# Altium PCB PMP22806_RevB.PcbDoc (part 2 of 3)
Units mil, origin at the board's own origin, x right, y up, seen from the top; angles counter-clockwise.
Board outline 5500 x 3040 mil, 4 copper layers (Top Layer, Signal Layer 1, Signal Layer 2, Bottom Layer), stack 61.2 mil thick; 196 components, 100 nets, 518 pads, 186 vias.
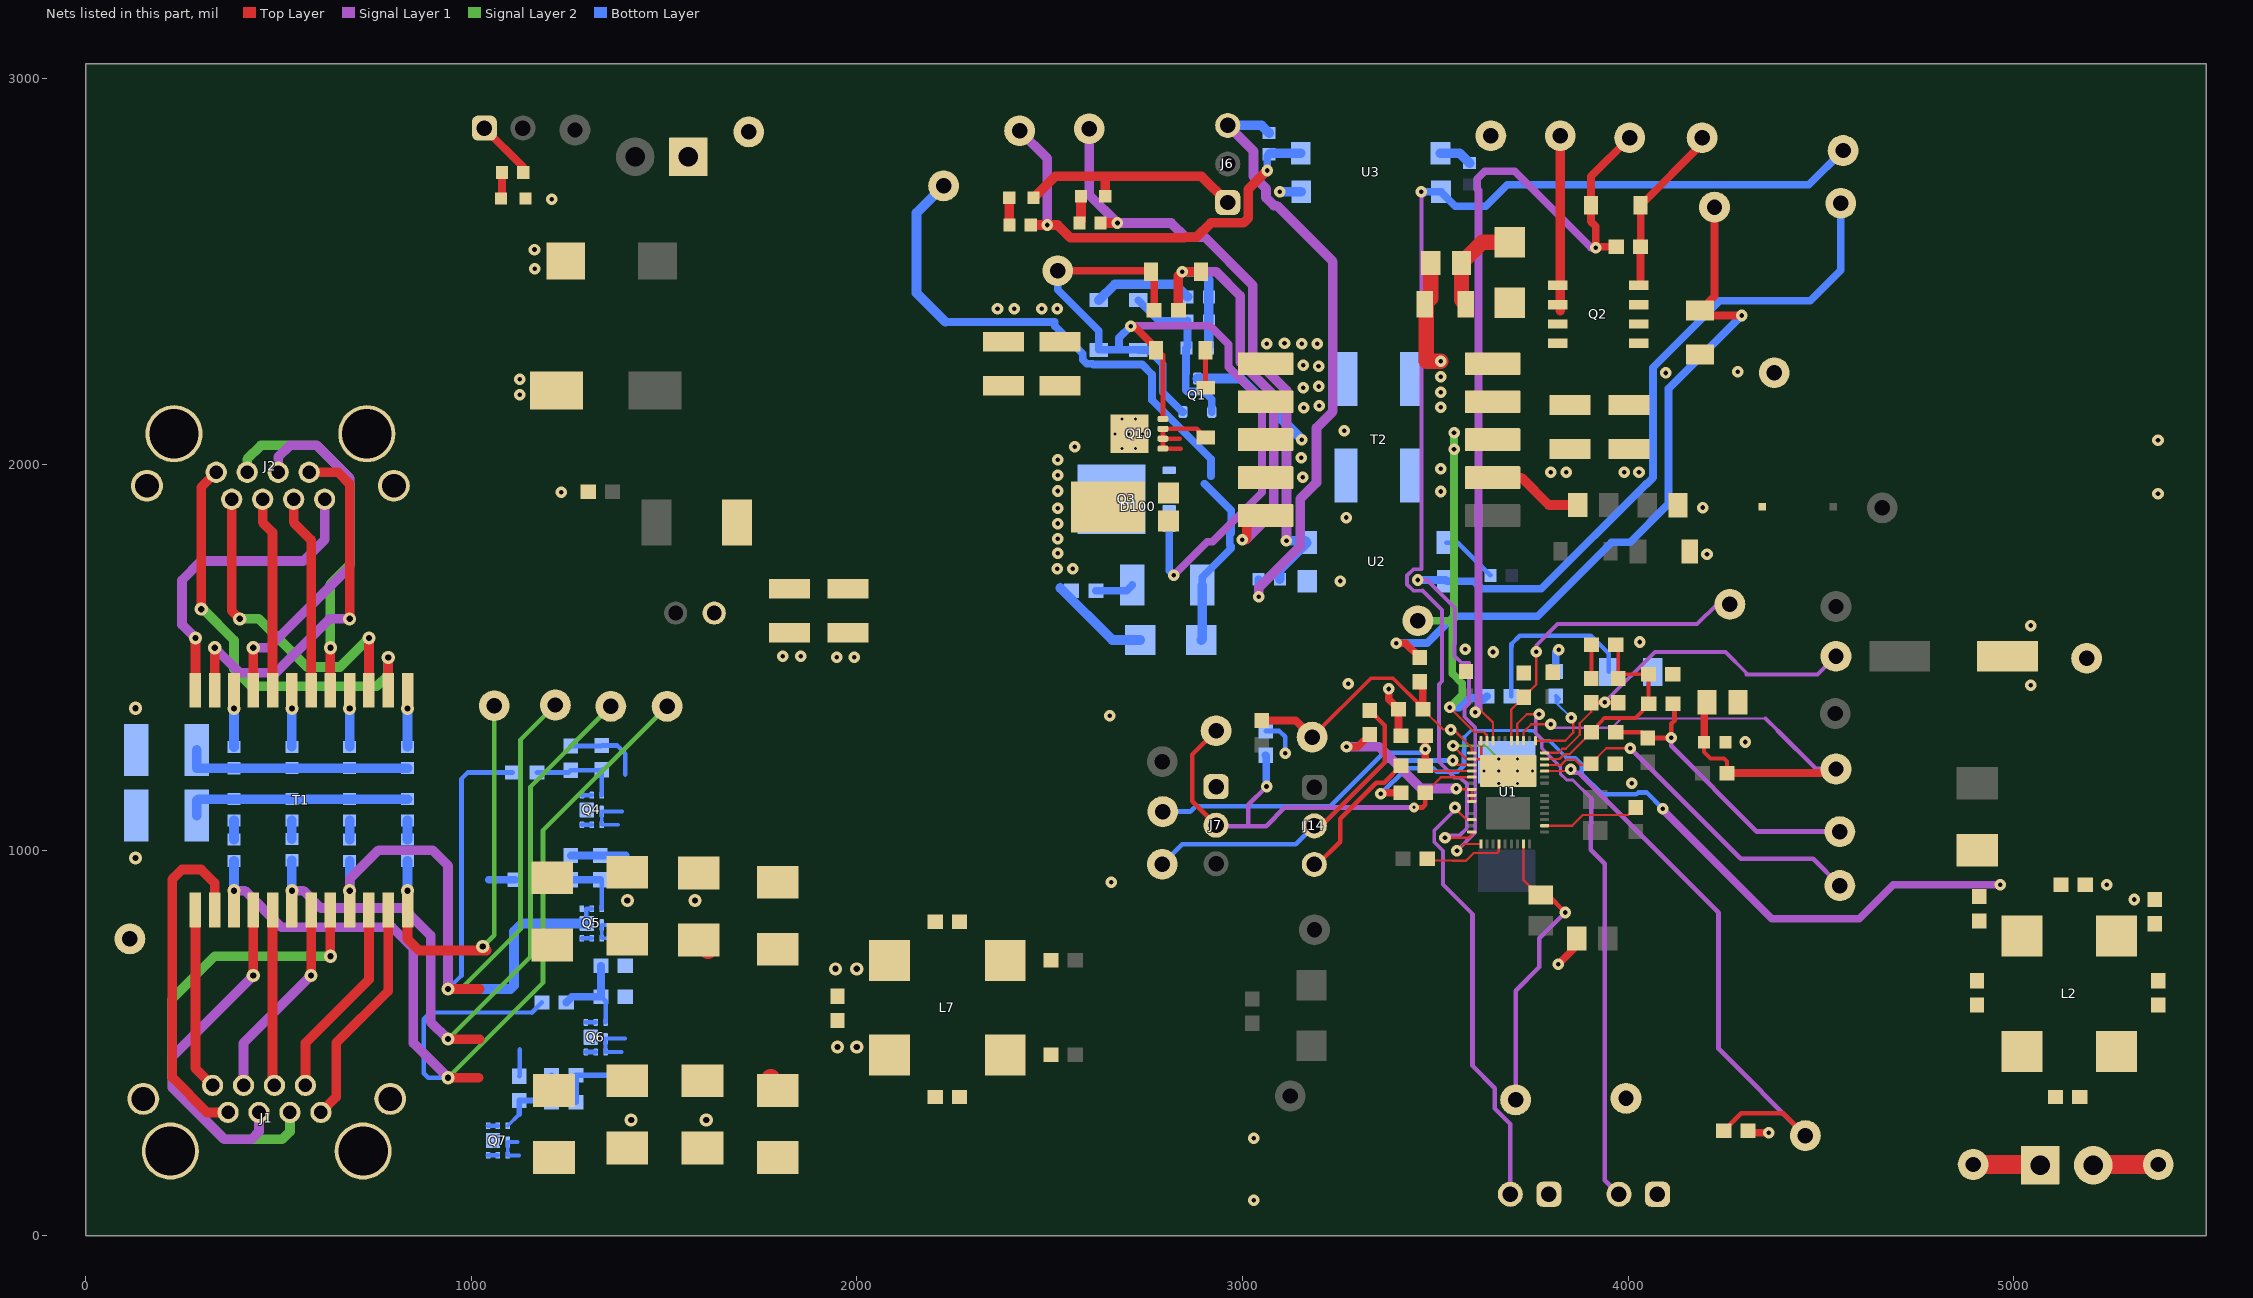
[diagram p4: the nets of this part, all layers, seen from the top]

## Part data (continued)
L4: library part CMP-0063890-1, "Inductor, Shielded Drum Core, Ferrite, 150 nH, 30 A, 0.000235 ohm, SMD", Manufacturer="Wurth Elektronik", Supplier Part Number 1=732-3698-1-ND, Value1="0.000235 ohm", Value2=30A, ValueDisplayed=150nH
Logo1: library part CMP-0074847-1, "FCC_disclaimer"
Logo2: library part CMP-0074769-1
Q1: library part CMP-0000326-2, "Transistor, PNP, 40 V, 0.2 A, SOT-23", Manufacturer="Diodes Inc.", Supplier Part Number 1=MMBT3906-FDICT-ND, Value1="0.2 A", Value2=400
Q2: library part CMP-0001058-1, "MOSFET, N-CH, 150 V, 4.6 A, PQFN08A", Alternate Manufacturer=None, Manufacturer="Fairchild Semiconductor", Supplier Part Number 1=FDMS86252CT-ND, Value1=0, Value2="11 nC"
Q3: library part CMP-0000708-1, "MOSFET, N-CH, 40 V, 15 A, DQJ0008A (VSONP-8)", Alternate Manufacturer=None, Manufacturer="Texas Instruments", Supplier Part Number 1=296-30572-1-ND, Value1=0.009, Value2="7.7 nC"
Q4 Q5 Q6 Q7: library part CMP-0000968-2, "MOSFET, N-CH, 100 V, 4.5 A, DQK0006C (WSON-6)", Alternate Manufacturer=None, Manufacturer="Texas Instruments"
Q10: library part CMP-0000589-2, "MOSFET, N-CH, 30 V, 19 A, DNH0008A (VSONP-8)", Alternate Manufacturer=None, Manufacturer="Texas Instruments", Supplier Part Number 1=296-39995-1-ND, Value1=0.006, Value2="13 nC"
R1 R2 R3 R4 R5 R6 R7 R8: library part CMP-0022590-4, "RES, 75.0, 1%, 0.1 W, AEC-Q200 Grade 0, 0603", Manufacturer=Vishay-Dale, PartNumber=CRCW060375R0FKEA, Power_W=100mW, Supplier Part Number 1=541-75.0HCT-ND, TempCo="100 ppm/C", Tolerance_%=1%, Value2=0.1W, Value_Code=75R0, ValueDisplayed=75.0
R9 R37: library part CMP-0021990-4, "RES, 100 k, 1%, 0.1 W, AEC-Q200 Grade 0, 0603", Manufacturer=Vishay-Dale, Power_W=100mW, Supplier Part Number 1=541-100KHCT-ND, TempCo="100 ppm/C", Tolerance_%=1%, Value2=0.1W, Value_Code=100k
R10: library part CMP-0022453-4, "RES, 4.42 k, 1%, 0.1 W, AEC-Q200 Grade 0, 0603", Manufacturer=Vishay-Dale, Power_W=100mW, Supplier Part Number 1=541-4.42KHCT-ND, TempCo="100 ppm/C", Tolerance_%=1%, Value2=0.1W, Value_Code=4k42, ValueDisplayed=4.42k
R11: library part CMP-0025821-4, "RES, 4.7, 5%, 0.1 W, AEC-Q200 Grade 0, 0603", Manufacturer=Vishay-Dale, PartNumber=CRCW06034R70JNEA, Power_W=100mW, Supplier Part Number 1=541-4.7GCT-ND, TempCo="200 ppm/C", Tolerance_%=5%, Value2=0.1W, Value_Code=4R70, ValueDisplayed=4.7
R12: library part CMP-0022458-4, "RES, 4.99 k, 1%, 0.1 W, AEC-Q200 Grade 0, 0603", Manufacturer=Vishay-Dale, Power_W=100mW, Supplier Part Number 1=541-4.99KHCT-ND, TempCo="100 ppm/C", Tolerance_%=1%, Value2=0.1W, Value_Code=4k99, ValueDisplayed=4.99k
R13: library part CMP-0018666-3, "RES, 39 k, 5%, 0.25 W, AEC-Q200 Grade 0, 1206", Manufacturer=Vishay-Dale, PartNumber=CRCW120639K0JNEA, Power_W=250mW, Supplier Part Number 1=541-39KECT-ND, TempCo="200 ppm/C", Tolerance_%=5%, Value2=0.25W, Value_Code=39k0, ValueDisplayed=39k
R14: library part CMP-0025821-4, "RES, 4.7, 5%, 0.1 W, AEC-Q200 Grade 0, 0603", Manufacturer=Vishay-Dale, Power_W=100mW, Supplier Part Number 1=541-4.7GCT-ND, TempCo="200 ppm/C", Tolerance_%=5%, Value2=0.1W, Value_Code=4R70, ValueDisplayed=4.7
R15 R17 R20 R21: "RES, 1.00 M, 1%, 0.1 W, AEC-Q200 Grade 0, 0603", Manufacturer=Vishay-Dale, PartNumber=CRCW06031M00FKEA, Power_W=100mW, Supplier Part Number 1=541-1.00MHCT-ND, TempCo="100 ppm/C", Tolerance_%=1%, Value2=0.1W, Value_Code=1M00, ValueDisplayed=1.00M
R16: library part CMP-0021831-3, "RES, 3.90, 1%, 0.125 W, AEC-Q200 Grade 0, 0805", Manufacturer=Panasonic, Power_W=125mW, Supplier Part Number 1=P3.9DCT-ND, TempCo="200 ppm/C", Tolerance_%=1%, Value2=0.125W, Value_Code=3R90, ValueDisplayed=3.90
R18: library part CMP-0017789-3, "RES, 0.12, 1%, 0.25 W, AEC-Q200 Grade 0, 1206", Manufacturer=Panasonic, Power_W=250mW, Supplier Part Number 1=P.39RCT-ND, TempCo="250 ppm/C", Tolerance_%=1%, Value2=0.25W, Value_Code=R390, ValueDisplayed=0.12
R19: library part CMP-0022895-5, "RES, 1.00 k, 1%, 0.1 W, 0603", Manufacturer=Yageo, Power_W=100mW, Supplier Part Number 1=311-1.00KHRCT-ND, TempCo="100 ppm/C", Tolerance_%=1%, Value2=0.1W, Value_Code=1k00, ValueDisplayed=1.00k
R22 R25 R26 R29: "RES, 232 k, 1%, 0.1 W, AEC-Q200 Grade 0, 0603", Manufacturer=Vishay-Dale, PartNumber=CRCW0603232KFKEA, Power_W=100mW, Supplier Part Number 1=541-232KHCT-ND, TempCo="100 ppm/C", Tolerance_%=1%, Value2=0.1W, Value_Code=232k
R24: library part CMP-0022447-4, "RES, 49.9 k, 1%, 0.1 W, AEC-Q200 Grade 0, 0603", Manufacturer=Vishay-Dale, Power_W=100mW, Supplier Part Number 1=541-49.9KHCT-ND, TempCo="100 ppm/C", Tolerance_%=1%, Value2=0.1W, Value_Code=49k9, ValueDisplayed=49.9k
R27: library part CMP-0021169-3, "RES, 31.6, 1%, 0.125 W, AEC-Q200 Grade 0, 0805", Manufacturer=Vishay-Dale, Power_W=125mW, Supplier Part Number 1=541-31.6CCT-ND, TempCo="100 ppm/C", Tolerance_%=1%, Value2=0.125W, Value_Code=31R6, ValueDisplayed=31.6
R28: library part CMP-0022951-5, "RES, 25.5 k, 1%, 0.1 W, 0603", Manufacturer=Yageo, Power_W=100mW, Supplier Part Number 1=311-25.5KHRCT-ND, TempCo="100 ppm/C", Tolerance_%=1%, Value2=0.1W, Value_Code=25k5, ValueDisplayed=25.5k
R30 R55 R56 R57 R58: library part CMP-0025874-4, "RES, 0, 5%, 0.1 W, AEC-Q200 Grade 0, 0603", Manufacturer=Panasonic, Power_W=100mW, Supplier Part Number 1=P0.0GCT-ND, TempCo="600 ppm/C", Tolerance_%=5%, Value2=0.1W, Value_Code=0000, ValueDisplayed=0
R31: library part CMP-0022003-4, "RES, 10.0, 1%, 0.1 W, AEC-Q200 Grade 0, 0603", Manufacturer=Vishay-Dale, Power_W=100mW, Supplier Part Number 1=541-10.0HCT-ND, TempCo="100 ppm/C", Tolerance_%=1%, Value2=0.1W, Value_Code=10R0, ValueDisplayed=10.0
R32: library part CMP-0022008-4, "RES, 110 k, 1%, 0.1 W, AEC-Q200 Grade 0, 0603", Manufacturer=Vishay-Dale, Power_W=100mW, Supplier Part Number 1=541-110KHCT-ND, TempCo="100 ppm/C", Tolerance_%=1%, Value2=0.1W, Value_Code=110k
R33 R36 R48 R59 R60 R61 R64 R65: library part CMP-0021998-4, "RES, 10.0 k, 1%, 0.1 W, AEC-Q200 Grade 0, 0603", Manufacturer=Vishay-Dale, Power_W=100mW, Supplier Part Number 1=541-10.0KHCT-ND, TempCo="100 ppm/C", Tolerance_%=1%, Value2=0.1W, Value_Code=10k0, ValueDisplayed=10.0k
R34: library part CMP-0025703-4, "RES, 10, 5%, 0.1 W, AEC-Q200 Grade 0, 0603", Manufacturer=Vishay-Dale, Power_W=100mW, Supplier Part Number 1=541-10GCT-ND, TempCo="200 ppm/C", Tolerance_%=5%, Value2=0.1W, Value_Code=10R0, ValueDisplayed=10
R35: library part CMP-0022944-5, "RES, 24.9 k, 1%, 0.1 W, 0603", Manufacturer=Yageo, Power_W=100mW, Supplier Part Number 1=311-24.9KHRCT-ND, TempCo="100 ppm/C", Tolerance_%=1%, Value2=0.1W, Value_Code=24k9, ValueDisplayed=24.9k
R38: library part CMP-0022452-4, "RES, 4.32 k, 1%, 0.1 W, AEC-Q200 Grade 0, 0603", Manufacturer=Vishay-Dale, Power_W=100mW, Supplier Part Number 1=541-4.32KHCT-ND, TempCo="100 ppm/C", Tolerance_%=1%, Value2=0.1W, Value_Code=4k32, ValueDisplayed=4.32k
R40: library part CMP-0022931-4, "RES, 237 k, 1%, 0.1 W, 0603", Manufacturer=Yageo, Power_W=100mW, Supplier Part Number 1=311-237KHRCT-ND, TempCo="100 ppm/C", Tolerance_%=1%, Value2=0.1W, Value_Code=237k
R41: library part CMP-0020539-3, "RES, 3.3 k, 5%, 0.125 W, AEC-Q200 Grade 0, 0805", Manufacturer=Vishay-Dale, Power_W=125mW, Supplier Part Number 1=541-3.3KACT-ND, TempCo="200 ppm/C", Tolerance_%=5%, Value2=0.125W, Value_Code=3k30, ValueDisplayed=3.3k
R42: library part CMP-0022532-4, "RES, 60.4 k, 1%, 0.1 W, AEC-Q200 Grade 0, 0603", Manufacturer=Vishay-Dale, Power_W=100mW, Supplier Part Number 1=541-60.4KHCT-ND, TempCo="100 ppm/C", Tolerance_%=1%, Value2=0.1W, Value_Code=60k4, ValueDisplayed=60.4k
R43: library part CMP-0018698-3, "RES, 51, 5%, 0.25 W, AEC-Q200 Grade 0, 1206", Manufacturer=Vishay-Dale, Power_W=250mW, Supplier Part Number 1=541-51ECT-ND, TempCo="200 ppm/C", Tolerance_%=5%, Value2=0.25W, Value_Code=51R0, ValueDisplayed=51
R47: library part CMP-0022445-4, "RES, 499 k, 1%, 0.1 W, AEC-Q200 Grade 0, 0603", Manufacturer=Vishay-Dale, Power_W=100mW, Supplier Part Number 1=541-499KHCT-ND, TempCo="100 ppm/C", Tolerance_%=1%, Value2=0.1W, Value_Code=499k
R68: library part CMP-0022587-4, "RES, 750 k, 1%, 0.1 W, AEC-Q200 Grade 0, 0603", Manufacturer=Vishay-Dale, Power_W=100mW, Supplier Part Number 1=541-750KHCT-ND, TempCo="100 ppm/C", Tolerance_%=1%, Value2=0.1W, Value_Code=750k
R69: library part CMP-0016180-3, "RES, 7.5, 5%, 0.75 W, AEC-Q200 Grade 0, 2010", Manufacturer=Vishay-Dale, Power_W=750mW, Supplier Part Number 1=541-7.5WCT-ND, TempCo="200 ppm/C", Tolerance_%=5%, Value2=0.75W, Value_Code=7R50, ValueDisplayed=7.5
T1: library part CMP-0030597-1, "Transformer, 350 uH, SMT", Manufacturer="Wurth Elektronik", ValueDisplayed=350uH
T2: library part CMP-0087730-2, "Flyback transformer for PoE applications", Manufacturer=LinkCom, PartNumber=LDT1069-50R, ValueDisplayed=70pF
TP1 TP6 TP12 TP18 TP43 TP45: library part CMP-0055137-1, "Test Point, Miniature, Red, TH", Color=Red, Manufacturer=Keystone, Supplier Part Number 1=36-5000-ND
TP2 TP7 TP8 TP14 TP30 TP37 TP38 TP44: library part CMP-0055138-1, "Test Point, Miniature, Black, TH", Color=Black, Manufacturer=Keystone, Supplier Part Number 1=36-5001-ND
TP3 TP5 TP9 TP10 TP15 TP16 TP17 TP19 TP20 TP22 TP23 TP24 TP25 TP26 TP27 TP32: library part CMP-0055139-1, "Test Point, Miniature, White, TH", Color=White, Manufacturer=Keystone, Supplier Part Number 1=36-5002-ND
TP4 TP11 TP13 TP21 TP28 TP29 TP33 TP34 TP39 TP40 TP42: library part CMP-0055140-1, "Test Point, Miniature, Orange, TH", Color=Orange, Manufacturer=Keystone, Supplier Part Number 1=36-5003-ND
U1: library part CMP-0089620-1, "IEEE 802.3bt Type 3 Class 1-4 PoE PD with No-Opto Flyback DC-DC Controller", Manufacturer="Texas Instruments", Operating Temperature Range="-40°C to +125°C", Switching Frequency=250kHz
U2 U3: library part CMP-0006165-3, "Optocoupler, 5 kV, 300-600% CTR, SMT", Manufacturer="Fairchild Semiconductor", Supplier Part Number 1=FOD817DS-ND, Voltage_Isolation_Vrms=5kV

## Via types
v1: diameter 30, hole 12, Top Layer to Bottom Layer, 104 vias
v2: diameter 34, hole 16, Top Layer to Bottom Layer, 37 vias
v3: diameter 30, hole 12, Top Layer to Bottom Layer, tented both sides, 22 vias
v4: diameter 19.68, hole 7.87, Top Layer to Bottom Layer, 19 vias
v5: diameter 20, hole 8, Top Layer to Bottom Layer, 2 vias
v6: diameter 26, hole 9, Top Layer to Bottom Layer, tented both sides, 1 vias
v7: diameter 19.68, hole 7.87, Top Layer to Bottom Layer, tented both sides, 1 vias

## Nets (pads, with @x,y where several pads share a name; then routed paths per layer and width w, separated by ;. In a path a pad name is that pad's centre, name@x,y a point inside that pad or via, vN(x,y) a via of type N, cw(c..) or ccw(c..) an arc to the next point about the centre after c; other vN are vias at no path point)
APD: J7.2 R9.1 R10.2 TP5.1 U1.5 | length 1238.6
  Top Layer w6: R9.1@3474.24,1149.02 3514.65,1189.42 U1.5@3594.85,1189.42
  Top Layer w12: J7.2@2931.67,1064.8 2870,1126.47 2870,1248.18 TP5.1@2931.67,1309.85 ; v6(3445,1110.86) 3467.65,1110.86 3474.24,1117.46 R9.1@3474.24,1149.02
  Signal Layer 1 w12: J7.2@2931.67,1064.8 2934.14,1062.33 3015,1062.33 ; v3(3062.64,1165.21) 3015,1117.57 3015,1062.33 ; v6(3445,1110.86) 3110.2,1110.86 3061.67,1062.33 3015,1062.33
  Bottom Layer w20: R10.2@3060.14,1246.23 3061.67,1244.7 v3@3061.67,1162.33
APDO: TP33.1 U1.13 U3.2 | length 3092.8
  Top Layer w6: v1(3525.32,1032.61) 3587.69,1032.61 3594.85,1039.77 U1.13@3594.85,1047.69
  Signal Layer 1 w10: v3(3464.21,2707.02) 3464.21,1728.56 3443.57,1728.56 3427.24,1712.23 3427.24,1689.14 3443.57,1672.81 3466.66,1672.81 3466.98,1673.12 3517.59,1622.5 3517.59,1438.04 3509.58,1430.03 3509.58,1229.5 3551.35,1187.72 3565.76,1187.72 3582.09,1171.4 3582.09,1097.31 3581.72,1096.93 3581.72,1056.62 3562.88,1037.77 3530.48,1037.77 v1(3525.32,1032.61)
  Signal Layer 1 w20: v3(3464.21,2707.02) v3@3468.23,2703
  Bottom Layer w20: v3(3464.21,2707.02) 3464.81,2707.61 U3.2@3514.8,2707.61 3552.41,2670 3630.97,2670 3686.46,2725.48 4468.69,2725.48 TP33.1@4557.62,2814.41
BSP: C1.1 C6.2 J1.9 J1.10 J1.11 J1.12 J2.9 J2.10 J2.11 J2.12 TP42.1
  other v2: 130,980 130,1367.99
CP: C42.1 T2.3 TP28.1 U1.44 | length 1093.4
  Top Layer w6: v3(3537.45,1370.21) 3601.07,1306.59 3625.76,1306.59 3633.28,1299.07 3633.28,1288.72 3633.28,1283.91 U1.44@3634.22,1283.91
  Top Layer w8: v3(3537.45,1370.21) v3@3540.49,1370.21
  Signal Layer 2 w20: TP28.1@3455.12,1595.17 3543.97,1595.17 ; v3@3543.52,1370.21 v3(3537.45,1370.21) 3570.33,1403.08 3570.33,1432.1 3543.97,1458.45 3543.97,1595.17 ; v1(3548.8,2082.66) v1(3548.8,2040) 3548.8,1600 3543.97,1595.17
  Bottom Layer w20: v3(3537.45,1370.21) 3562.28,1370.21 3574.68,1382.61 3576.55,1380.75 3590.53,1394.73 3617.76,1394.73 3623.52,1388.97 C42.1@3634.04,1399.49
CS: C25.1 R19.1 R68.2 TP15.1 U1.1 | length 787.1
  Top Layer w6: C25.1@3467.92,1365.64 3520.75,1312.8 v1(3540,1312.8) 3547.18,1312.8 3594.85,1265.13 U1.1@3594.85,1252.41
  Top Layer w10: TP15.1@3180.79,1293.42 3333.44,1446.07 3390.76,1446.07 C25.1@3467.92,1368.92
  Top Layer w20: R68.2@3050,1336.5 3137.72,1336.5 TP15.1@3180.79,1293.42 ; R19.1@3459.5,1436.98 3467.92,1428.56 3467.92,1368.92 C25.1@3467.92,1365.64
GND: C11.1 C16.2 C17.2 C18.2 C19.2 C20.2 C21.2 C22.2 C28.1 D21.1 J4.1 T2.9 T2.10 TP14.1 U2.3 U3.3 | length 56.3
  Bottom Layer w25: v1(3096.51,2707.02) 3103.99,2707.02 3104.59,2707.61 U3.3@3152.6,2707.61
  other v1: 1947.81,1500.48 1993.23,1500.48 1808.23,1502.82 1855,1502.61 3253.78,1697.96 3269.22,1862.61 1233.98,1928.62 3264.22,2087.61 3159.03,2147.61 3199.22,2152.61 1126.42,2180.75 3157.6,2199.58 3198.21,2202.61 1126.42,2221.72 3197.47,2254.81 3157.6,2257.61 3063.49,2313.09 3154.22,2313.52 3194.56,2313.52 3109.22,2314.71 2365,2403.72 2408.27,2403.72 2480,2403.72 2519.81,2404.1 1164.96,2507.93 1164.22,2557.61 1208.88,2687.8
NetC1_2: C1.2 R1.2 R2.2 R7.2 R8.1 | length 593.9
  Bottom Layer w25: C1.2@288.74,1260 288.74,1212.44 R8.1@385,1212.44 385.32,1212.76 R7.2@535,1212.76 R2.2@685,1212.76 R1.2@835,1212.76
NetC2_2: C2.2 R3.2 | length 49.9
  Bottom Layer w25: C2.2@835,1027.56 R3.2@835,1077.44
NetC3_2: C3.2 R4.2 | length 49.9
  Bottom Layer w25: C3.2@685,1027.56 R4.2@685,1077.44
NetC4_2: C4.2 R5.2 | length 48.2
  Bottom Layer w25: C4.2@535,1029.21 R5.2@535,1077.44
NetC5_2: C5.2 R6.2 | length 49.9
  Bottom Layer w25: C5.2@385,1027.56 R6.2@385,1077.44
NetC6_1: C6.1 R3.1 R4.1 R5.1 R6.1 | length 586.6
  Bottom Layer w25: C6.1@288.74,1090 288.74,1128.82 292.48,1132.56 R6.1@385,1132.56 R5.1@535,1132.56 R4.1@685,1132.56 R3.1@835,1132.56
NetC7_1: C7.1 J3.1 L2.2 R30.1 TP43.1 | length 174.4
  Top Layer w50: TP43.1@4895,185 5066.79,185 J3.1@5068.66,183.14
NetC7_2: C7.2 J3.2 L2.3 R56.1 TP44.1 | length 169.1
  Top Layer w50: J3.2@5206.66,183.14 5208.52,185 TP44.1@5375,185
NetC8_1: C8.1 D1.2 L1.2 R9.2 | length 2033.3
  Top Layer w20: v3(3359.22,1146.24) 3362,1149.02 R9.2@3411.25,1149.02
  Signal Layer 1 w20: v1@4089.22,1106.25 4373.14,822.33 4599.6,822.33 4687.68,910.41 v1(4965,910.41)
  Bottom Layer w8: 3574.93,1293.09 3591.84,1310 3742.55,1310 3742.69,1309.86 3754.12,1309.86 3781.02,1282.96 3797.11,1282.96
  Bottom Layer w10: 3797.11,1282.96 3841.77,1238.3
  Bottom Layer w12: v3(3359.22,1146.24) 3425.72,1212.74 3494.58,1212.74 3503.58,1203.74 3557.85,1203.74 3574.76,1220.65 3574.76,1258.49 3574.93,1258.66 3574.93,1293.09 ; 3841.77,1238.3 3863.38,1238.3 3880.29,1221.39 3880.29,1197.31 3932.8,1144.8 4021.18,1144.8 4026.03,1149.65 4048.04,1149.65 v1(4089.94,1107.75)
NetC9_1: C9.1 D2.1 D3.1 D4.1 D11.1 L7.2 R57.1
  other v2: 1415,300 1609.69,300 1945,692.44 2000,692.44
NetC9_2: C9.2 C24.2 C27.2 C29.2 C31.2 D13.2 D14.2 D15.2 D16.2 L7.3 Q4.4 Q4.7 Q5.4 Q5.7 Q6.4 Q6.7 Q7.4 Q7.7 R22.1 R25.1 R26.1 R29.1 R58.1 | length 1033.6
  Bottom Layer w10: 1120,243.4 Q7.7@1094.97,243.4 Q7.4@1094.97,208.76 1123.76,208.76 ; 1381.24,1066.1 Q4.4@1338.59,1066.1 Q4.7@1338.59,1100.74 1391.26,1100.74 ; 1390.65,476.61 Q6.4@1348.59,476.61 Q6.7@1348.59,511.26 1399.59,511.26 ; 1397.41,806.26 Q5.7@1338.54,806.26 Q5.4@1338.54,771.61 1400.51,771.61
  Bottom Layer w12: C24.2@1258.75,1270.37 1337.62,1270.37 R22.1@1338.75,1271.5 1378.5,1271.5 1399.77,1250.23 1399.77,1196.46
  Bottom Layer w15: C31.2@1271.5,346.26 C31.2@1271.5,346.26 R29.1@1271.54,416.62 1386.62,416.62
  Bottom Layer w20: C27.2@1258.75,986.5 R25.1@1335,986.5 1401.23,986.5
  other v2: 1950,490 2000,490 1405,870 1580.32,869.59
NetC10_1: C10.1 D17.1 R11.1 R12.2 R31.2 T2.6 | length 1400.9
  Top Layer w25: R31.2@2834.07,2399.9 2834.07,2489.07 2844.71,2499.71 D17.1@2892.3,2499.71 ; v1(3000,1805) 3007.65,1805 3011.14,1808.49 3011.14,1850.87 3043.1,1850.87 T2.6@3060.09,1867.86
  Signal Layer 1 w25: v1(2844.05,2500.37) 2931.46,2500.37 2994.41,2437.42 2994.41,2265.72 3081.35,2178.78 3081.35,1878.7 3007.65,1805 v1(3000,1805)
  Bottom Layer w25: v1(2844.05,2500.37) 2891.28,2500.37 2912.97,2478.68 R11.1@2912.97,2434.9 C10.1@2912.97,2372.69 2912.97,2305.49 R12.2@2910.17,2302.69
NetC10_2: C10.2 D6.2 Q1.1 R12.1 | length 441.8
  Bottom Layer w20: D6.2@2730,2426.33 2783.64,2372.69 C10.2@2857.85,2372.69 2857.85,2305.49 R12.1@2855.05,2302.69 2853.52,2301.17 2853.52,2236.47 2852.83,2235.79 2852.83,2193.63 2856.88,2189.58 2900.42,2189.58 2920.61,2169.39 Q1.1@2920.61,2136.59
NetC11_2: C11.2 C13.1 C14.1 C15.2 L3.2 R13.2 T2.2 | length 301.1
  Top Layer w40: C15.2@3488.21,2522.61 3488.21,2431.34 R13.2@3473.06,2416.2 3476.38,2412.88 3476.38,2267.61 v1(3514.8,2267.61)
  other v1: 3514.65,2148.39 3514.65,2187.61 3514.22,2227.61
NetC15_1: C15.1 D7.1 R13.1 | length 258.4
  Top Layer w40: R13.1@3579.36,2416.2 3568.21,2427.35 C15.1@3568.21,2522.61 3622.26,2576.67 D7.1@3693.21,2576.67
NetC18_1: C18.1 C19.1 C20.1 C21.1 C44.1 D20.1 D100.3 J11.1 L4.1 Q3.5 Q3.6 Q3.7 Q3.8 Q3.9@2660.47,1910 Q10.5 Q10.6 Q10.7 Q10.8 Q10.9 | length 263.7
  Bottom Layer w25: 2527.66,1680 2662.66,1545 D20.1@2735.47,1545
  other v1: 2519.81,1730 2560.15,1730 2521.18,1769.86 2521.18,1807.79 2521.18,1847.04 2521.18,1887.01 2521.03,1931.47 2521.03,1972.18 2521.03,2012.15 2564.94,2046.12
  other v4: 2687.64,2041.43 2723.27,2041.43 2705.46,2079.81 2741.09,2079.81 2687.64,2118.2 2723.27,2118.2
  other v7: 2669.83,2079.81
NetC24_1: C24.1 Q4.3 R15.1 R22.2 | length 236.6
  Bottom Layer w12: R15.1@1170.74,1201.52 1252.89,1201.52 C24.1@1258.75,1207.38 1337.62,1207.38 R22.2@1338.75,1208.5 1338.75,1143.03 Q4.3@1338.59,1142.87
NetC27_1: C27.1 Q5.3 R17.1 R25.2 | length 235.1
  Bottom Layer w12: R25.2@1335,923.5 1338.54,919.97 Q5.3@1338.54,848.39
  Bottom Layer w20: R17.1@1176.5,923.5 C27.1@1258.75,923.5 R25.2@1335,923.5
NetC29_1: C29.1 Q6.3 R20.1 R26.2 | length 248.1
  Bottom Layer w12: R26.2@1336.78,620.29 1348.59,608.48 Q6.3@1348.59,553.39
  Bottom Layer w20: R20.1@1246.5,605 1261.79,620.29 R26.2@1336.78,620.29 C29.1@1336.78,700
NetC31_1: C31.1 Q7.3 R21.1 R29.2 | length 224.5
  Bottom Layer w10: Q7.3@1094.97,285.53 1125,315.56
  Bottom Layer w15: 1125,315.56 R21.1@1125,350.68 1204.08,350.68 1204.08,412.15 R29.2@1208.55,416.62
NetC34_1: C34.1 R34.2 R35.2 TP9.1 | length 793.8
  Top Layer w12: C34.1@3968.33,1305.8 4035.83,1305.8 R34.2@4050.71,1290.92 4110.7,1290.92 v3(4111.83,1292.05) 4111.83,1327.62 4120.42,1336.2 R35.2@4120.42,1381.11
  Signal Layer 1 w12: v3(4111.83,1292.05) 4111.83,1270.36 4333.82,1048.37 TP9.1@4549.22,1048.37
NetC34_2: C34.2 C36.1 R35.1 R37.2 R38.1 U1.34 | length 598.5
  Top Layer w6: U1.34@3783.83,1236.67 3822.45,1236.67 3834.95,1249.17 3848.71,1249.17 C34.2@3905.34,1305.8
  Top Layer w10: C34.2@3905.34,1305.8 3939.22,1343.28 4019.6,1343.28 4057.42,1381.11 R35.1@4053.5,1385.03 ; R37.2@3976.45,1532.61 R37.2@3967.96,1532.61 3974.57,1525.99 C36.1@3974.57,1445.4 3985.27,1456.11 R38.1@4052.95,1456.11 4053.5,1455.55 R35.1@4053.5,1385.03 ; R35.1@4052.95,1385.58 R35.1@4053.5,1385.03 ; R35.1@4053.5,1380 R35.1@4053.5,1385.03
NetC35_1: C35.1 R37.1 | length 87.2
  Top Layer w10: C35.1@3904.57,1445.58 3904.96,1445.97 R37.1@3904.96,1532.61
NetC35_2: C35.2 C36.2 TP19.1 U1.35 | length 983.8
  Top Layer w6: U1.35@3783.83,1252.41 3818.57,1252.41 3829.28,1263.12 3838.71,1263.12 3874.78,1299.19 3874.78,1329 3904.57,1358.79 C35.2@3904.57,1382.58
  Top Layer w10: C35.2@3897.7,1382.58 C35.2@3904.57,1382.58
  Top Layer w12: C35.2@3904.57,1382.58 3974.39,1382.58 C36.2@3974.57,1382.41
  Signal Layer 1 w10: v3(3939.22,1383.63) 4069.49,1513.9 4252.71,1513.9 4306.59,1460.02 4306.59,1455.2 4491.53,1455.2 TP19.1@4539.22,1502.89
NetC39_1: C39.1 J14.2 TP16.1 U1.3 | length 1321.5
  Top Layer w6: v1(3545.89,1232.61) 3556.64,1221.85 3590.04,1221.85 3590.98,1220.92 U1.3@3594.85,1220.92
  Top Layer w12: J14.2@3186.48,1063.15 3205.04,1063.15 3369.39,1227.49 3369.39,1323.39 C39.1@3330.1,1362.69
  Bottom Layer w12: TP16.1@2792.1,963.44 2843.66,1015 3138.33,1015 J14.2@3186.48,1063.15 3205.04,1063.15 3374.51,1232.61 v1(3545.89,1232.61)
NetC41_2: C41.2 TP26.1 U1.40 | length 820.2
  Top Layer w6: U1.40@3697.21,1283.91 3697.21,1364.85 C41.2@3729.22,1396.86 3761.85,1429.48 v1(3761.85,1515.11)
  Signal Layer 1 w10: v1(3761.85,1515.11) 3761.85,1530.58 3817.53,1586.27 4179.22,1586.27 4230.56,1637.61 TP26.1@4264.22,1637.61
NetC42_2: C42.2 R43.2 | length 463.2
  Bottom Layer w12: C42.2@3697.03,1399.49 3697.03,1526.77 3697.86,1527.6 3697.86,1534.78 3719.35,1556.27 3903.73,1556.27 3949.84,1510.16 R43.2@3949.84,1462.61
NetC44_2: C44.2 R69.2 | length 100.3
  Bottom Layer w20: C44.2@2620.18,1672.97 2699.88,1672.97 R69.2@2714.45,1687.53
NetD5_1: D5.1 D6.1 D17.2 D19.1 Q1.2 Q3.4 Q10.4 R31.1 TP13.1 | length 2417.4
  Top Layer w12: D19.1@2775.3,2302.69 2793.94,2284.06 Q10.4@2793.94,2118.2
  Top Layer w20: TP13.1@2521.03,2502.61 2760.46,2502.61 D17.2@2763.36,2499.71 2771.08,2491.99 R31.1@2771.08,2399.9 ; v3(2710,2358.55) 2719.45,2358.55 D19.1@2775.3,2302.69
  Signal Layer 1 w20: v3(2710,2358.55) 2724.94,2358.55 2726.4,2360 2916.06,2360 2964.03,2312.02 2964.03,2253.14 3050.97,2166.2 3050.97,1928.11 2922.5,1799.65 2909.15,1799.65 v1(2822.11,1712.61)
  Bottom Layer w20: TP13.1@2521.03,2502.61 2521.03,2453.52 2627.76,2346.79 D5.1@2627.76,2297.4 2680,2297.4 ; v3(2710,2358.55) 2680,2328.55 2680,2297.4 ; Q3.4@2810.08,1835 2810.08,1724.64 v1(2822.11,1712.61) ; Q1.2@2845.81,2136.59 2844.31,2136.59 2793.29,2187.61 2793.29,2260.35 2756.24,2297.4 D6.1@2730,2297.4 2680,2297.4
NetD5_2: D5.2 R11.2 | length 260.7
  Bottom Layer w25: D5.2@2627.76,2426.34 2669.03,2467.61 2825.13,2467.61 R11.2@2857.85,2434.9
NetD7_2: D7.2 Q2.5 Q2.6 Q2.7 Q2.8 T2.1 TP21.1 | length 453.4
  Top Layer w25: 3824.22,2399.21 TP21.1@3824.22,2852.61
NetD8_1: D8.1 R14.1 TP24.1 U1.43 | length 2289.7
  Top Layer w6: v3(3604.22,1357.61) 3614.67,1357.61 3618.91,1361.85 3649.97,1330.8 U1.43@3649.97,1283.91
  Top Layer w20: R14.1@3969.48,2564.71 3918.47,2564.71 v1(3916.38,2562.61) 3916.38,2617.81 3903.74,2630.45 D8.1@3903.74,2672.93 3903.74,2747.13 TP24.1@4004.22,2847.61
  Signal Layer 1 w20: v3(3604.22,1357.61) 3612.24,1365.63 3612.24,2710.98 3609.22,2713.99 3609.22,2741.23 3628.48,2760.48 3706.31,2760.48 3904.18,2562.61 v1(3916.38,2562.61)
  Signal Layer 2 w20: v3(3604.22,1357.61) v3@3612.24,1365.63
NetD8_2: D8.2 Q2.4 R14.2 TP25.1 | length 451
  Top Layer w20: Q2.4@4027.62,2464.71 4032.47,2469.56 R14.2@4032.47,2564.71 4032.68,2564.91 D8.2@4032.68,2672.93 4191.94,2832.19 TP25.1@4191.94,2847.61
NetD18_1: D18.1 D20.2 D100.1 D100.2 Q1.3 Q3.1 Q3.2 Q3.3 Q10.1 Q10.2 Q10.3 R69.1 T2.7 T2.8 TP11.1 | length 2413.1
  Top Layer w12: 2837.75,2067.02 Q10.2@2793.94,2067.02 ; 2840.12,2041.43 Q10.1@2793.94,2041.43 Q10.2@2793.94,2067.02 ; D18.1@2904.38,2070.24 2882.01,2092.61 Q10.3@2793.94,2092.61 Q10.2@2793.94,2067.02
  Bottom Layer w20: 2230,2370 2513.3,2370 2513.3,2359.52 2585.87,2286.95 2585.87,2271.99 2596.34,2261.52 2611.3,2261.52 2613.28,2259.54 2740.06,2259.54 2765.41,2234.19 2765.41,2167.61 2918.29,2014.73 2918.29,1970 ; R69.1@2895.55,1687.53 2895.55,1707.67 2970.75,1782.87 2970.75,1787.76 2967.13,1791.38 2967.13,1818.62 2970.75,1822.24 2970.75,1880.89 2901.65,1950
  Bottom Layer w25: TP11.1@2225,2722.59 2155,2652.59 2155,2445 2230,2370 ; Q1.3@2883.21,2223.2 2995.72,2223.2 v1(3154.22,2064.71) ; D20.2@2892.95,1545 2895.55,1547.6 R69.1@2895.55,1687.53
  other v1: 3156.61,1967.61 3152.6,2017.61
NetD18_2: D18.2 D19.2 | length 103.6
  Top Layer w12: D19.2@2904.24,2302.69 2904.38,2302.55 D18.2@2904.38,2199.18
NetD21_2: D21.2 R59.1 | length 68.3
  Top Layer w20: D21.2@1077.72,2690.36 1080.16,2692.8 R59.1@1080.16,2757.61
NetD22_1: D22.1 R60.2 | length 70.7
  Top Layer w25: D22.1@2395.5,2691.83 2395.5,2621.75 R60.2@2395.94,2621.31
NetD22_2: D22.2 D23.2 J6.1 | length 606.8
  Top Layer w25: D22.2@2458.49,2691.83 2514.27,2747.61 2644.22,2747.61 ; D23.2@2644.49,2695.76 2644.49,2747.34 2644.22,2747.61 ; J6.1@2962.05,2679.62 2894.05,2747.61 2832.56,2747.61 2644.22,2747.61
NetD23_1: D23.1 R61.2 | length 71.1
  Top Layer w25: R61.2@2577.17,2626.47 2581.5,2630.8 D23.1@2581.5,2695.76
NetJ1_1: J1.1 T1.23 | length 597.3
  Top Layer w25: J1.1@610.47,319.96 650,359.49 650,500 785,635 T1.23@785,844.96
NetJ1_2: J1.2 T1.22 | length 523.1
  Top Layer w25: J1.2@570.32,390.04 570.32,500 735,664.68 T1.22@735,844.96
NetJ1_3: J1.3 T1.20 | length 1224.7
  Top Layer w25: v2(635,725) T1.20@635,844.96
  Signal Layer 2 w25: J1.3@530.16,319.96 530.16,270.32 509.84,250 360,250 225,385 225,615 335,725 v2(635,725)
NetJ1_4: J1.4 T1.17 | length 457
  Top Layer w25: T1.17@485,844.96 485,395.04 J1.4@490,390.04
NetJ1_5: J1.5 T1.16 | length 886
  Top Layer w25: v2(435,675) T1.16@435,844.96
  Signal Layer 1 w25: v2(435,675) 225,465 225,385 360,250 429.84,250 449.84,270 J1.5@449.84,319.96
NetJ1_6: J1.6 T1.19 | length 527.5
  Top Layer w25: v2(585,675) T1.19@585,844.96
  Signal Layer 1 w25: J1.6@409.69,390.04 409.69,499.69 v2(585,675)
NetJ1_7: J1.7 T1.14 | length 901.7
  Top Layer w25: T1.14@335,844.96 335,915 300,950 250,950 225,925 225,410 315.04,319.96 J1.7@369.53,319.96
NetJ1_8: J1.8 T1.13 | length 473.3
  Top Layer w25: T1.13@285,844.96 285,434.41 J1.8@329.37,390.04
NetJ2_1: J2.1 T1.2 | length 1125
  Top Layer w25: v2(300,1625) 300,1941.18 J2.1@338.9,1980.08 ; T1.2@785,1415.04 v2(785,1500)
  Signal Layer 2 w25: v2(300,1625) 304.45,1625 385,1544.45 385,1470 430,1425 755,1425 785,1455 v2(785,1500)
NetJ2_2: J2.2 T1.3 | length 871.5
  Top Layer w25: J2.2@379.06,1910 379.06,1620.94 v2(400,1600) ; T1.3@735,1415.04 v2(735,1550)
  Signal Layer 2 w25: v2(400,1600) 449.53,1600 574.53,1475 660,1475 v2(735,1550)
NetJ2_3: J2.3 T1.5 | length 920.6
  Top Layer w25: T1.5@635,1415.04 v2(635,1525)
  Signal Layer 2 w25: J2.3@419.21,1980.08 419.21,2014.21 455,2050 600,2050 685,1965 685,1740 635,1690 v2(635,1525)
NetJ2_4: J2.4 T1.8 | length 505.6
  Top Layer w25: J2.4@459.37,1910 459.37,1850 485,1824.37 T1.8@485,1415.04
NetJ2_5: J2.5 T1.9 | length 949.7
  Top Layer w25: T1.9@435,1415.04 v2(435,1525)
  Signal Layer 1 w25: v2(435,1525) 475,1525 685,1735 685,1965 600,2050 530,2050 499.53,2019.53 J2.5@499.53,1980.08
NetJ2_6: J2.6 T1.6 | length 513.7
  Top Layer w25: J2.6@539.68,1910 539.68,1850 585,1804.68 T1.6@585,1415.04
NetJ2_7: J2.7 T1.11 | length 1012.5
  Top Layer w25: T1.11@335,1415.04 v2(335,1525) ; J2.7@579.84,1980.08 654.92,1980.08 685,1950 v2(685,1600)
  Signal Layer 1 w25: v2(335,1525) 400,1460 492.6,1460 632.6,1600 v2(685,1600)
NetJ2_8: J2.8 T1.12 | length 818
  Top Layer w25: T1.12@285,1415.04 v2(285,1550)
  Signal Layer 1 w25: v2(285,1550) 250,1585 250,1700 300,1750 565,1750 620,1805 J2.8@620,1910
NetJ6_3: J6.3 R64.2 R65.2 | length 1579.5
  Signal Layer 1 w25: J6.3@2962.05,2879.62 3028.85,2812.82 3028.85,2747.96 3061.14,2715.66 3061.14,2692.36 3081.86,2671.64 3089.34,2671.64 3234.59,2526.39 3234.59,2137.96 3191.99,2095.35 3191.99,1952.96 3149.59,1910.56 3149.59,1787.96 3041.99,1680.35 v1(3041.99,1657.61)
  Bottom Layer w20: v1(3041.99,1657.61) R65.2@3041.99,1702.61
  Bottom Layer w25: J6.3@2962.05,2879.62 3049.36,2879.62 R64.2@3069.22,2859.76
NetJ14_3: J14.3 R40.1 | length 365.5
  Top Layer w12: J14.3@3186.48,963.15 3194.63,963.15 3253.78,1022.3 3253.78,1081.63 3347.26,1175.11 3367.35,1175.11 R40.1@3411.25,1219.02
NetJ15_1: J15.1 R59.2 | length 156.9
  Top Layer w20: J15.1@1034.22,2872.61 1135.28,2771.55 R59.2@1135.28,2757.61
NetJ17_2: J17.2 U1.39 | length 1461.2
  Top Layer w6: U1.39@3712.96,1283.91 3712.96,1328.08 3737.49,1352.61 v3(3769.22,1352.61)
  Signal Layer 1 w8: v3@3765.72,1352.61 v3(3769.22,1352.61) 3760.71,1344.1 3760.71,1303.27 3776.18,1287.8 3776.18,1264.68 3824.55,1216.32 3824.55,1198.29 3840.29,1182.55 3856.21,1182.55 3904.22,1134.54
  Signal Layer 1 w12: 3904.22,1134.54 3903.74,1001.35 3939.79,965.3 3939.79,144.35 J17.2@3976.26,107.87
NetJ18_2: J18.2 U1.11 | length 1165.3
  Top Layer w6: v1(3551.33,1110.68) 3551.33,1108.48 3579.69,1080.12 3594.85,1080.12 U1.11@3594.85,1079.18
  Signal Layer 1 w10: v1(3551.33,1110.68) 3551.33,1105.07 3497.45,1051.18 3497.45,1021.06 3520,998.51 3520,910.95 3596.67,834.27
  Signal Layer 1 w12: 3596.67,834.27 3596.67,440.94 3654.52,383.1 3654.52,330.24 3694.73,290.03 J18.2@3694.73,107.87
NetL1_1: L1.1 L2.1 R30.2
NetL2_4: L2.4 L5.1 R56.2
NetL6_1: L6.1 L7.1 R57.2
NetL7_4: L7.4 L8.1 R58.2
NetQ2_1: Q2.1 Q2.2 Q2.3 R18.1 R19.2 TP27.1 | length 1895.7
  Top Layer w20: v1(3398.6,1536.7) 3422.77,1536.7 R19.2@3459.5,1499.97 ; TP27.1@4224.22,2667.61 4224.22,2436.98 R18.1@4186.94,2399.7 4199.98,2386.65 v1(4294.56,2386.65)
  Bottom Layer w20: v1(3398.6,1536.7) 3406.15,1536.7 3406.75,1537.3 3479.09,1537.3 3548.72,1606.93 3765.71,1606.93 3957.3,1798.52 4005.43,1798.52 4105,1898.09 4105,2197.09 v1(4294.56,2386.65)
NetR1_1: R1.1 T1.1 | length 147.2
  Top Layer w25: v2(835,1367.36) T1.1@835,1415.04
  Bottom Layer w25: R1.1@835,1267.87 v2(835,1367.36)
NetR2_1: R2.1 T1.4 | length 147.2
  Top Layer w25: v2(685,1367.36) T1.4@685,1415.04
  Bottom Layer w25: R2.1@685,1267.87 v2(685,1367.36)
NetR7_1: R7.1 T1.7 | length 147.2
  Top Layer w25: v2(535,1367.36) T1.7@535,1415.04
  Bottom Layer w25: R7.1@535,1267.87 v2(535,1367.36)
NetR8_2: R8.2 T1.10 | length 147.5
  Top Layer w25: v2(385,1367.36) T1.10@385,1415.04
  Bottom Layer w25: R8.2@385,1267.56 v2(385,1367.36)
NetR16_2: R16.2 T2.4 | length 250.6
  Top Layer w25: T2.4@3648.67,1966.28 3723.28,1966.28 3794.4,1895.16 R16.2@3869.78,1895.16
NetR24_2: R24.2 U1.17 | length 217.7
  Top Layer w6: R24.2@3479.19,977.61 3483.43,973.37 3544.81,973.37 3545.61,972.56 3579.87,972.56 3599.92,992.61 3660.97,992.61 3664.78,996.42 3664.78,1015.26 U1.17@3665.72,1016.19
NetR27_2: R27.2 TP29.1 U1.21 | length 776.1
  Top Layer w6: U1.21@3728.71,1016.19 3728.71,922.67 3767.43,883.95 R27.2@3773.43,883.95
  Top Layer w12: R27.2@3773.43,883.95 3791.63,883.95 v1(3837.18,838.4)
  Signal Layer 1 w12: TP29.1@3708.39,352.55 3708.39,635.47 3770,697.08 3770,771.22 v1(3837.18,838.4)
NetR28_2: R28.2 U1.24 | length 255.7
  Top Layer w6: U1.24@3783.83,1063.44 3855.05,1063.44 3882.74,1091.13 3999.7,1091.13 R28.2@4019.73,1111.15
NetR36_1: R36.1 U3.1 | length 86.1
  Bottom Layer w25: U3.1@3513.82,2807.61 3563.43,2807.61 R36.1@3589.22,2781.82
NetR40_2: R40.2 R42.2 TP22.1 U1.4 | length 960.1
  Top Layer w6: R40.2@3474.24,1219.02 3488.09,1205.17 U1.4@3594.85,1205.17
  Top Layer w20: R40.2@3474.24,1219.02 R42.2@3474.24,1296.91
  Bottom Layer w12: TP22.1@2799.62,1106.2 TP22.1@2793.64,1100.21 2865.21,1100.21 2879.11,1114.11 3227.9,1114.11 3366.27,1252.48 3464.54,1252.48 v3(3474.03,1261.98)
NetR47_2: R47.2 TP32.1 U1.32 | length 1535.2
  Top Layer w6: U1.32@3783.83,1205.17 3847.16,1205.17 v3(3851.42,1209.43)
  Top Layer w12: R47.2@4248.23,272.61 4293.64,318.02 4401.98,318.02 TP32.1@4460,260
  Signal Layer 1 w12: v3@3853.48,1211.48 v3(3851.42,1209.43) 3860.42,1200.43 3872.14,1200.43 4234.71,837.86 4234.71,485.29 TP32.1@4460,260
NetR48_1: R48.1 U2.1 | length 149
  Bottom Layer w12: U2.1@3529.41,1797.61 3558.21,1797.61 R48.1@3643.21,1712.61
NetR55_1: R55.1 U1.36 | length 251.7
  Top Layer w6: U1.36@3760.2,1283.91 3837.12,1283.91 3858.14,1304.93 3858.14,1337.62 3852.44,1343.32 v1@3846.73,1337.61
  Bottom Layer w6: R55.1@3812.78,1400.25 3812.78,1383.04 v1(3852.5,1343.32)
  Bottom Layer w10: R55.1@3812.78,1400.25 3820.93,1392.1 3816.67,1392.1 R55.1@3816.67,1384.99
NetR60_1: R60.1 R64.1 TP39.1 U3.4 | length 1144.8
  Top Layer w25: R60.1@2451.06,2621.31 v1(2494.22,2621.31) 2521.03,2621.31 2554.24,2588.1 2849.86,2588.1 2851.59,2589.83 2881.36,2589.83 2918.29,2626.76 3002.97,2626.76 3014.9,2638.7 3014.9,2713.29 v1(3064.22,2762.61)
  Signal Layer 1 w25: TP39.1@2422.24,2865.69 2494.22,2793.71 v1(2494.22,2621.31)
  Bottom Layer w20: v1(3064.22,2762.61) 3064.22,2799.64 R64.1@3069.22,2804.64
  Bottom Layer w25: R64.1@3069.22,2804.64 3072.19,2807.61 U3.4@3151.61,2807.61
NetR61_1: R61.1 R65.1 TP40.1 U2.4 | length 1614
  Top Layer w25: R61.1@2632.29,2626.47 v1(2675.99,2626.47)
  Signal Layer 1 w25: TP40.1@2602.77,2870.85 2602.77,2699.69 v1(2675.99,2626.47) 2815.42,2626.47 2852.05,2589.83 2902.33,2589.83 3027.28,2464.88 3027.28,2279.33 3114.22,2192.4 v3(3114.22,1802.61)
  Bottom Layer w25: R65.1@3097.1,1702.61 3097.1,1727.51 U2.4@3167.2,1797.61 3162.2,1802.61 v3(3114.22,1802.61)
PGND: C8.2 C12.2 C13.2 C14.2 C25.2 C28.2 C33.1 C37.2 C38.1 C39.2 C40.2 C41.1 C43.2 C45.1 D25.1 J7.1 J17.1 J18.1 L5.2 R10.1 R18.2 R33.2 R38.2 R41.1 R42.1 R43.1 R47.1 R55.2 TP7.1 TP30.1 TP37.1 TP38.1 U1.2 U1.7 U1.8 U1.9 U1.45 U1.46 | length 1279.2
  Top Layer w6: v1(3546.06,1270.62) 3580.01,1236.67 U1.2@3594.85,1236.67 3595.79,1235.73 3619.41,1235.73 3619.41,1282.97 U1.45@3618.47,1283.91 ; v1(3554.22,1159.85) 3556.14,1157.93 U1.7@3594.85,1157.93 U1.8@3594.85,1142.18 U1.9@3594.85,1126.43 ; U1.46@3626.35,1213.04 3689.34,1213.04 3689.34,1235.73 U1.46@3664.73,1235.73
  Top Layer w20: v1@3279.39,1268.37 3298.77,1268.37 C39.2@3330.1,1299.69 ; v3(3379.22,1418.19) 3379.22,1391.34 C25.2@3404.92,1365.64 3404.92,1303.24 R42.1@3411.25,1296.91 ; v1(3819.22,704.26) 3867.37,752.41 C43.2@3867.37,771.27 ; R47.1@4311.23,272.61 4316.23,267.61 v1(4364.71,267.61)
  Signal Layer 1 w25: v1(3270,1268.37) 3354.4,1268.37 3462.92,1159.85 v1(3554.22,1159.85)
  Signal Layer 2 w6: v1(3546.06,1270.62) 3630.98,1270.62 v4(3664.73,1236.86)
  Bottom Layer w12: R10.1@3060.14,1309.22 3095.78,1309.22 3111.19,1293.81 v3(3111.19,1251.59) v3@3111.19,1245
  Bottom Layer w20: R55.2@3812.78,1463.24 v1@3812.78,1514.05
  other v1: 3029.82,92.61 3029.22,252.61 5312.45,872.23 5241.42,910.61 2659.79,917.24 4009.22,1173.68 4304.22,1280.6 2655.94,1349.13 5044.22,1427.56 3274.66,1432.1 3649.97,1513.91 3820,1520 5044.18,1582.61 4204.73,1767.61 4193.74,1888.57 5374.22,1924.01 3514.8,1930.17 3800,1979.69 3840,1980.08 3990.41,1979.69 4028.38,1979.69 3514.8,1989.03 5374.22,2062.61 4284.22,2241.05
  other v3: 3577.95,1521.51 4030,1540 4097.48,2237.61
  other v4: 3664.73,1173.48 3713.94,1173.48 3626.35,1205.17 3664.73,1205.17 3713.94,1205.17 3752.33,1205.17 3713.94,1236.86
PR12: C2.1 D2.2 D13.1 Q4.1 Q4.2 Q4.5 Q4.6 Q4.8 R17.2 T1.24 TP1.1 | length 1187.7
  Top Layer w25: v2(835,895) 835,770 865,740 1030.01,740.09 v2@1040,740.09
  Top Layer w50: D13.1@1396.01,760 D13.1@1405,768.99
  Signal Layer 2 w12: v2(1030,750) 1060,780 TP1.1@1059.88,1374.5
  Bottom Layer w12: Q4.6@1287.41,1066.1 Q4.5@1313,1066.1 ; Q4.1@1287.41,1142.87 Q4.2@1313,1142.87
  Bottom Layer w20: 1046.5,923.5 R17.2@1113.5,923.5
  Bottom Layer w25: v2(835,895) C2.1@835,972.44
PR36: C3.1 D3.2 D14.1 Q5.1 Q5.2 Q5.5 Q5.6 Q5.8 R15.2 T1.21 TP2.1 | length 3047.7
  Top Layer w25: T1.21@685,844.96 v2(685,895) ; v2(940,640) 1021.89,640
  Top Layer w50: D14.1@1590,766.99 D14.1@1614,742.99
  Signal Layer 1 w25: v2(685,895) 685,925 760,1000 900,1000 940,960 v2@940,650
  Signal Layer 2 w12: v2(940,640) 973.37,640 1128,794.63 1128,1286.11 TP2.1@1218.39,1376.5
  Bottom Layer w12: v2(940,640) 975,675 975,1185 991.52,1201.52 R15.2@1107.75,1201.52 ; Q5.6@1287.36,771.61 Q5.5@1312.95,771.61 ; Q5.8@1298.43,810 1298.43,848.39 Q5.2@1312.95,848.39
  Bottom Layer w25: v2(685,895) C3.1@685,972.44 ; v2(940,640) 1101.89,640 1111,649.11 1111,789.5 1131.5,810 1298.43,810 Q5.8@1300.15,810
PR45: C4.1 D4.2 D15.1 Q6.1 Q6.2 Q6.5 Q6.6 Q6.8 R21.2 T1.18 TP3.1 | length 2091.6
  Top Layer w25: T1.18@535,844.96 v2(535,895) ; v2(940,510) 1021.89,510
  Top Layer w50: D15.1@1776.75,407.01 D15.1@1795,388.76
  Signal Layer 1 w25: v2(535,895) 565,895 610,850 823.7,850 895,778.7 895,554.49 939.49,510 v2(940,510)
  Signal Layer 2 w12: v2(940,510) 1153.98,723.98 1153.98,1164.8 TP3.1@1362.2,1373.03
  Bottom Layer w12: R21.2@1125,413.67 1126.3,414.97 1126.3,483.03 ; Q6.6@1297.41,476.61 Q6.5@1323,476.61 ; Q6.1@1297.41,553.39 Q6.2@1323,553.39
  Bottom Layer w25: v2(535,895) C4.1@535,974.09
PR78: C5.1 D11.2 D16.1 Q7.1 Q7.2 Q7.5 Q7.6 Q7.8 R20.2 T1.15 TP4.1 | length 2897.1
  Top Layer w25: T1.15@385,844.96 v2(385,895) ; v2(940,410) 1019.72,410
  Signal Layer 1 w25: v2(385,895) 413,895 508,800 795.37,800 850,745.37 850,500 v2(940,410)
  Signal Layer 2 w12: v2(940,410) 1186.23,656.24 1186.23,1051.26 TP4.1@1508,1373.03
  Bottom Layer w12: v2@940,417.11 v2(940,410) 888.35,410 876.59,421.76 876.59,561.59 895,580 1156.8,578.3 R20.2@1183.5,605 ; Q7.6@1043.79,208.76 Q7.5@1069.38,208.76 ; Q7.1@1043.79,285.53 Q7.2@1069.38,285.53
  Bottom Layer w25: v2(385,895) C5.1@385,972.44
SS: C33.2 TP10.1 U1.33 | length 942.6
  Top Layer w6: U1.33@3783.83,1220.92 3826.32,1220.92 3840.7,1235.3 3862.14,1235.3 3876.52,1220.92 3900.34,1220.92 C33.2@3903.84,1224.42 3943.63,1264.21 v3(4005.5,1264.21)
  Signal Layer 1 w12: v3(4005.5,1264.21) 4292.1,977.61 4394.22,977.61 4479.98,977.61 TP10.1@4549.22,908.37
T2P: TP34.1 U1.14 U2.2 | length 2679.5
  Top Layer w6: v1(3556.33,998.44) 3574.09,1016.19 U1.14@3618.47,1016.19
  Signal Layer 1 w10: v1(3455.12,1700.68) 3478.83,1700.68 3551.49,1628.03 3551.49,1535.89 3550.07,1534.47 3550.07,1503.78 3567.82,1486.03 3587.23,1486.03 3587.23,1380.04 3576.35,1369.16 3576.35,1346.06 3603.63,1318.78 3603.63,1045.74 v1(3556.33,998.44)
  Signal Layer 1 w20: v1@3555.03,999.74 v1(3556.33,998.44)
  Bottom Layer w20: v1(3455.12,1700.68) 3527.32,1700.68 U2.2@3530.39,1697.61 3600.45,1697.61 3620.06,1678 3775.1,1678 4046.83,1949.74 4048.34,1949.74 4065,1966.39 4065,2223.6 4064.6,2223.99 4064.6,2251.23 4238.11,2424.74 4472.77,2424.74 4551.67,2503.63 TP34.1@4551.67,2677.61
UV: C45.2 R32.1 R33.1 TP23.1 U1.38 | length 1428.4
  Top Layer w6: U1.38@3728.71,1283.91 3728.71,1306.62 3748.79,1326.71 v1(3799.56,1326.71)
  Top Layer w10: R33.1@4197.44,1280 4197.44,1254.4 4214.08,1237.77 4248.43,1237.77 4256.5,1229.7 R32.1@4256.5,1200
  Top Layer w20: R33.1@4197.44,1280 4197.44,1376.07 C45.2@4205,1383.63 ; R32.1@4256.5,1200 4528.75,1200 TP23.1@4539.31,1210.56
  Signal Layer 1 w6: v1(3799.56,1326.71) 3808.83,1317.44 3958.09,1317.44 3982.32,1341.68 4356.6,1341.68
  Signal Layer 1 w10: 4356.6,1341.68 4388.43,1309.85
  Signal Layer 1 w12: 4388.43,1309.85 4487.72,1210.56 TP23.1@4539.31,1210.56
